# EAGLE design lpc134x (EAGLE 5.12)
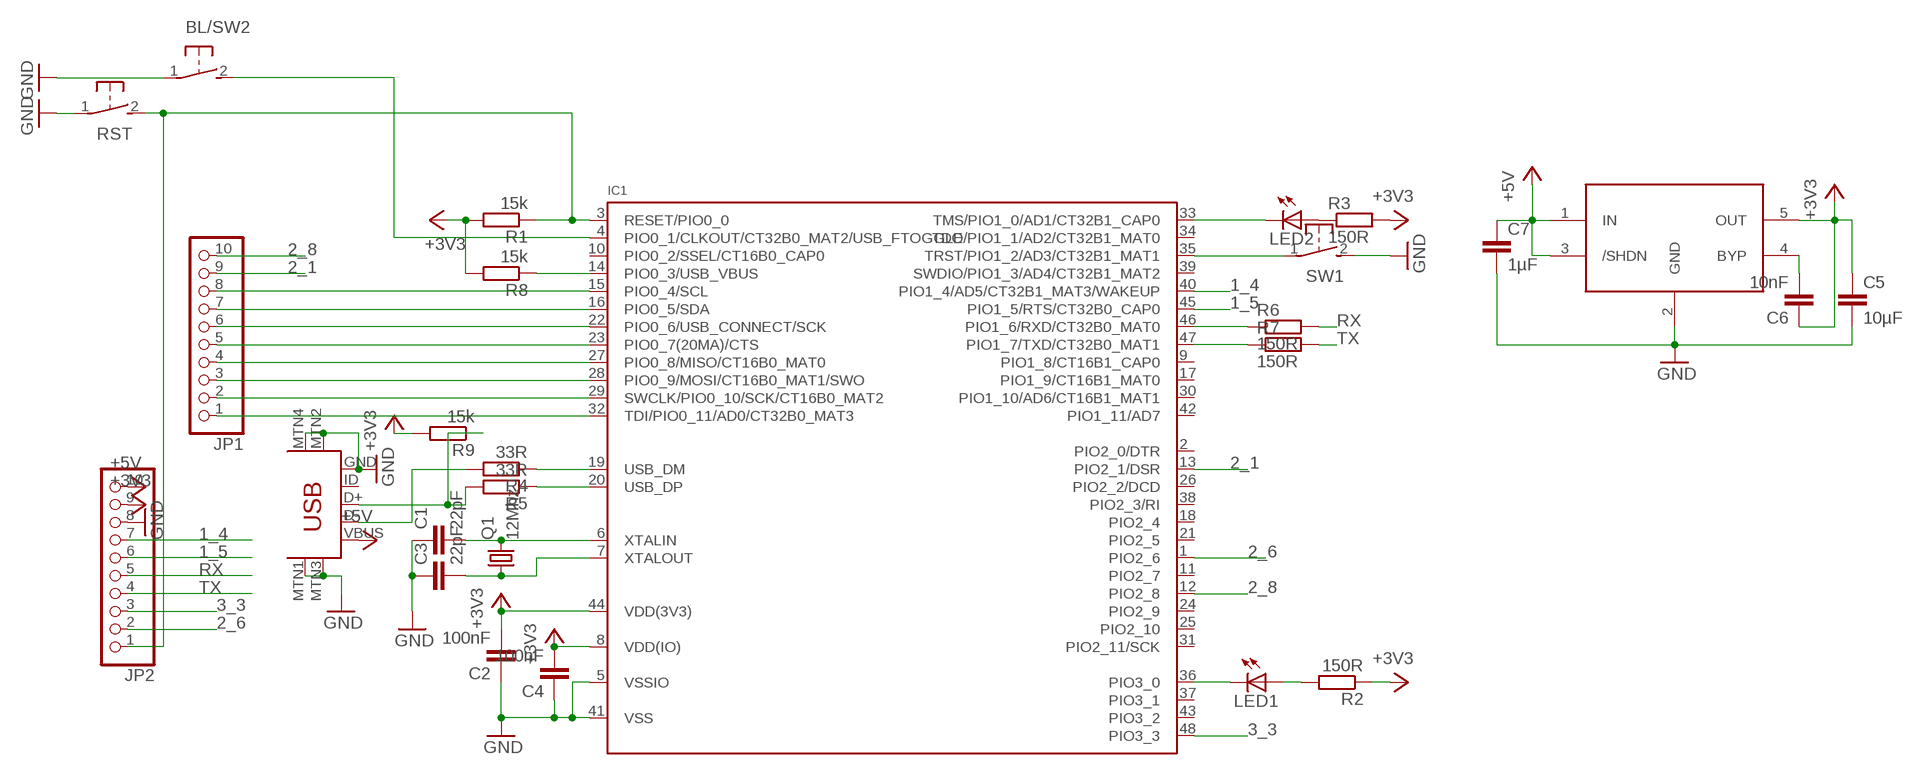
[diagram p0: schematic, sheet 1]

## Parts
BL/SW2  SWITCH_MCTAEF  [SWITCH_MCTAEF]
C1  22pF  C-EUC0402  [C0402]
C2  100nF  C-EUC0402  [C0402]
C3  22pF  C-EUC0402  [C0402]
C4  100nF  C-EUC0402  [C0402]
C5  10µF  CAP0805  [0805]
C6  10nF  C-EUC0402  [C0402]
C7  1µF  CAP0805  [0805]
IC1  LPC1343_QFP  [LQFP48]
IC2  LT1761  [SOT23-5L]
JP1  PINHD-1X10_2.54  [1X10]
JP2  PINHD-1X10_2.54  [1X10]
LED1  LEDCHIPLED_0805  [CHIPLED_0805]
LED2  LEDCHIPLED_0805  [CHIPLED_0805]
Q1  12Mhz  MT-OSCILLATOR  [MT]
R1  15k  R-EU_R0402  [R0402]
R2  150R  R-EU_R0402  [R0402]
R3  150R  R-EU_R0402  [R0402]
R4  33R  R-EU_R0402  [R0402]
R5  33R  R-EU_R0402  [R0402]
R6  150R  R-EU_R0402  [R0402]
R7  150R  R-EU_R0402  [R0402]
R8  15k  R-EU_R0402  [R0402]
R9  15k  R-EU_R0402  [R0402]
RST  SWITCH_MCTAEF  [SWITCH_MCTAEF]
SW1  SWITCH_MCTAEF  [SWITCH_MCTAEF]
U$1  USB-MINIB-5PIN  [USB-MINIB]

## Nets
1_4: IC1.40(PIO1_4/AD5/CT32B1_MAT3/WAKEUP) JP2.7
1_5: IC1.45(PIO1_5/RTS/CT32B0_CAP0) JP2.6
2_1: IC1.13(PIO2_1/DSR) JP1.9
2_6: IC1.1(PIO2_6) JP2.2
2_8: IC1.12(PIO2_8) JP1.10
3_3: IC1.48(PIO3_3) JP2.3
+3V3: C2.2 C4.2 C5.1 C6.1 IC1.8(VDD(IO)) IC1.44(VDD(3V3)) IC2.5(OUT) JP2.9 R1.2 R2.1 R3.2 R8.2 R9.2
+5V: C7.1 IC2.1(IN) IC2.3(/SHDN) JP2.10 U$1.VBUS
GND: BL/SW2.1 C1.1 C2.1 C3.1 C4.1 C5.2 C7.2 IC1.5(VSSIO) IC1.41(VSS) IC2.2(GND) JP2.8 RST.1 SW1.2 U$1.GND U$1.MTN1(MTN2) U$1.MTN2(MTN3) U$1.MTN3(MTN1) U$1.MTN4
N$1: IC1.32(TDI/PIO0_11/AD0/CT32B0_MAT3) JP1.1
N$2: IC1.29(SWCLK/PIO0_10/SCK/CT16B0_MAT2) JP1.2
N$3: C3.2 IC1.7(XTALOUT) Q1.1
N$4: C1.2 IC1.6(XTALIN) Q1.3
N$5: IC1.28(PIO0_9/MOSI/CT16B0_MAT1/SWO) JP1.3
N$6: IC1.27(PIO0_8/MISO/CT16B0_MAT0) JP1.4
N$7: IC1.3(RESET/PIO0_0) JP2.1 R1.1 RST.2
N$8: IC1.23(PIO0_7(20MA)/CTS) JP1.5
N$9: IC1.22(PIO0_6/USB_CONNECT/SCK) JP1.6
N$10: R5.2 R9.1 U$1.D+
N$11: R4.2 U$1.D-
N$12: IC1.14(PIO0_3/USB_VBUS) R8.1
N$14: IC1.19(USB_DM) R4.1
N$16: IC1.46(PIO1_6/RXD/CT32B0_MAT0) R6.1
N$17: IC1.47(PIO1_7/TXD/CT32B0_MAT1) R7.1
N$18: LED1.A R2.2
N$19: IC1.36(PIO3_0) LED1.C
N$20: IC1.35(TRST/PIO1_2/AD3/CT32B1_MAT1) SW1.1
N$21: BL/SW2.2 IC1.4(PIO0_1/CLKOUT/CT32B0_MAT2/USB_FTOGGLE)
N$22: LED2.A R3.1
N$23: IC1.33(TMS/PIO1_0/AD1/CT32B1_CAP0) LED2.C
N$24: IC1.20(USB_DP) R5.1
N$43: C6.2 IC2.4(BYP)
RX: JP2.5 R6.2
SCL: IC1.15(PIO0_4/SCL) JP1.8
SDA: IC1.16(PIO0_5/SDA) JP1.7
TX: JP2.4 R7.2
Unconnected: IC1.2(PIO2_0/DTR) IC1.9(PIO1_8/CT16B1_CAP0) IC1.10(PIO0_2/SSEL/CT16B0_CAP0) IC1.11(PIO2_7) IC1.17(PIO1_9/CT16B1_MAT0) IC1.18(PIO2_4) IC1.21(PIO2_5) IC1.24(PIO2_9) IC1.25(PIO2_10) IC1.26(PIO2_2/DCD) IC1.30(PIO1_10/AD6/CT16B1_MAT1) IC1.31(PIO2_11/SCK) IC1.34(TDO/PIO1_1/AD2/CT32B1_MAT0) IC1.37(PIO3_1) IC1.38(PIO2_3/RI) IC1.39(SWDIO/PIO1_3/AD4/CT32B1_MAT2) IC1.42(PIO1_11/AD7) IC1.43(PIO3_2) U$1.ID

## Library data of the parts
BL/SW2 RST SW1 = seb:SWITCH_MCTAEF
C1-C4 C6 = rcl:C-EU: CAPACITOR, European symbol
C5 C7 = SparkFun:CAP: Capacitor
IC1 = microbuilder:LPC1343_QFP: LPC1343 72 MHz 32-bit ARM Cortex-M3 microcontroller. 32 kB Flash, 8 kB SRAM, USB Device Mouser: 771-LPC1343FBD48151 Digikey: 568-4945-ND; DIGIKEY#: 568-4945-ND; MANF: NXP; MANF#: LPC1343FBD48,151
IC2 = seb:LT1761
JP1 JP2 = pinhead-2:PINHD-1X10: PIN HEADER
LED1 LED2 = led:LED: LED
Q1 = seb:MT-OSCILLATOR
R1-R9 = rcl:R-EU_: RESISTOR, European symbol
U$1 = SparkFun:USB-MINIB: Mini-USB "B" connector with 5th pin broken out. Created new symbol breaking out 5th "ID" pin in mini/micro USB connector spec. See: http://en.wikipedia.org/wiki/Mini_usb#Cables. Uses same footprint as 4-pin symbol. Also added pins to connect to mounting / shield pads if required (probably not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

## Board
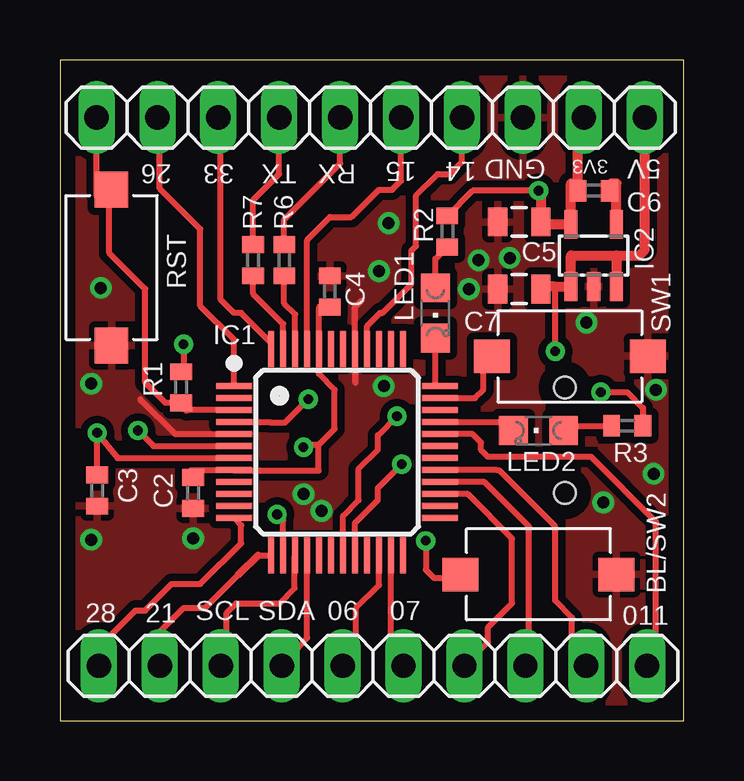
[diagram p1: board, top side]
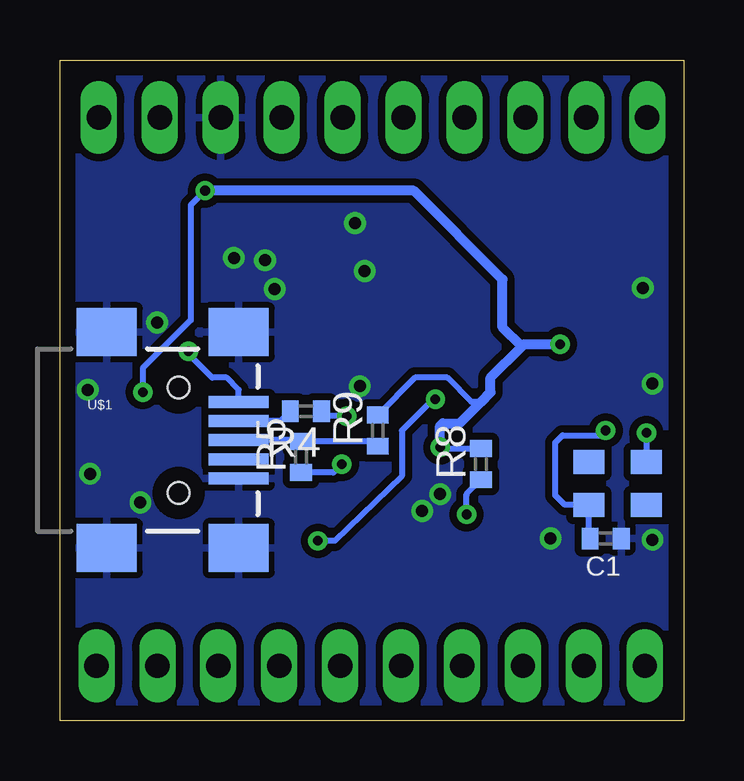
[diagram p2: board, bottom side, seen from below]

Size 26 x 27.55 mm. Coordinates in mm from the lower left corner, seen from the top.
Outline: 0,0 26,0 26,27.55 0,27.55 0,0
Copper layers (1*16): Top 0.035mm / dielectric 1.5mm / Bottom 0.035mm
Design rules "default *": minimum track width 10mil, minimum drill 24mil, track to track 8mil, track to pad 8mil, pad to pad 8mil, via to via 8mil, smd to smd 8mil, copper to edge 25mil, drill to drill 8mil, minimum pad ring 10mil, minimum via ring 8mil, stop-mask expansion 4mil, vias tented up to drill 40mil, thermal gap 10mil

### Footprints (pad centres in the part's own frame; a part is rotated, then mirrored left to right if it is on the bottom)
SWITCH_MCTAEF = smd 1.5 x 1.4: 1 -3.25,0; 2 3.25,0
C0402 = smd 0.7 x 0.9: 1 -0.65,0; 2 0.65,0
0805 = smd 0.8 x 1.2: 1 -0.9,0; 2 0.9,0
LQFP48 = smd 1.5 x 0.25: 1 -4.3,2.75; 2 -4.3,2.25; 3 -4.3,1.75; 4 -4.3,1.25; 5 -4.3,0.75; 6 -4.3,0.25; 7 -4.3,-0.25; 8 -4.3,-0.75; 9 -4.3,-1.25; 10 -4.3,-1.75; 11 -4.3,-2.25; 12 -4.3,-2.75; 25 4.3,-2.75; 26 4.3,-2.25; 27 4.3,-1.75; 28 4.3,-1.25; 29 4.3,-0.75; 30 4.3,-0.25; 31 4.3,0.25; 32 4.3,0.75; 33 4.3,1.25; 34 4.3,1.75; 35 4.3,2.25; 36 4.3,2.75 | smd 0.25 x 1.5: 13 -2.75,-4.3; 14 -2.25,-4.3; 15 -1.75,-4.3; 16 -1.25,-4.3; 17 -0.75,-4.3; 18 -0.25,-4.3; 19 0.25,-4.3; 20 0.75,-4.3; 21 1.25,-4.3; 22 1.75,-4.3; 23 2.25,-4.3; 24 2.75,-4.3; 37 2.75,4.3; 38 2.25,4.3; 39 1.75,4.3; 40 1.25,4.3; 41 0.75,4.3; 42 0.25,4.3; 43 -0.25,4.3; 44 -0.75,4.3; 45 -1.25,4.3; 46 -1.75,4.3; 47 -2.25,4.3; 48 -2.75,4.3
SOT23-5L = smd 0.55 x 1.2: 1 -0.95,-1.3; 2 0,-1.3; 3 0.95,-1.3; 4 0.95,1.3; 5 -0.95,1.3
1X10 = drill 1.016 long: 1 -11.43,0; 2 -8.89,0; 3 -6.35,0; 4 -3.81,0; 5 -1.27,0; 6 1.27,0; 7 3.81,0; 8 6.35,0; 9 8.89,0; 10 11.43,0
CHIPLED_0805 = smd 1.2 x 1.2: A 0,-1.05; C 0,1.05
MT = smd 1.3 x 1: 1 1.2,0.9; 2 -1.2,0.9; 3 -1.2,-0.9; 4 1.2,-0.9
R0402 = smd 0.7 x 0.9: 1 -0.65,0; 2 0.65,0
USB-MINIB = smd 2.5 x 0.5: D+ 2.5,0; D- 2.5,0.8; GND 2.5,-1.6; ID 2.5,-0.8; VBUS 2.5,1.6 | smd 2.5 x 2: MTN1 -3,4.5; MTN2 2.5,4.5; MTN3 -3,-4.5; MTN4 2.5,-4.5 | hole 0.9: 0,2.2; 0,-2.2

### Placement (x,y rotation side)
BL/SW2  19.95,6.1 180 top
C1  3.25,7.6 180 bottom
C2  5.55,9.5 90 top
C3  1.55,9.6 90 top
C4  11.25,17.9 270 top
C5  19.15,20.8 180 top
C6  22.25,22.1 0 top
C7  19.15,18 180 top
IC1  11.55,11.2 0 top
IC2  22.25,19.4 0 top
JP1  13.05,2.29 180 top
JP2  12.95,25.15 0 top
LED1  15.65,17 180 top
LED2  19.95,12.1 90 top
Q1  2.75,9.9 0 bottom
R1  5.05,13.9 90 top
R2  16.15,20.4 270 top
R3  23.65,12.3 0 top
R4  15.75,12.9 180 bottom
R5  15.95,11 90 bottom
R6  9.35,19.2 90 top
R7  8.05,19.2 90 top
R8  8.45,10.7 90 bottom
R9  12.75,12.1 90 bottom
RST  2.15,18.9 90 top
SW1  21.25,15.2 0 top
U$1  21.05,11.7 0 bottom

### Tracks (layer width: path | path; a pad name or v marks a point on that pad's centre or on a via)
1_4
  Top 0.254: JP2.7 16.76,23.31 16.25,22.8 15.75,22.8 14.85,21.9 14.85,19.8 14.65,19.6 14.65,18.2 13.45,17 13.35,17 12.8,16.45 IC1.40
1_5
  Top 0.254: JP2.6 14.22,22.51 13.85,22.14 13.29,22.14 12.15,21 11.25,21 10.3,20.05 10.3,20.01 IC1.45
2_1
  Top 0.254: JP1.9 4.16,3.71 5.15,4.7 6.05,4.7 7.45,6.1 | 8.25,6.9 IC1.13
  Top 0.305: 7.45,6.1 8.25,6.9
2_6
  Top 0.254: JP2.2 4.16,25.05 4.16,22.19 5.85,20.5 5.85,17.3 7.23,15.92 7.25,15.9 IC1.1
2_8
  Top 0.254: JP1.10 1.62,3.07 3.15,4.6 3.55,4.6 4.65,5.7 5.85,5.7 7.55,7.4 7.55,8.15 IC1.12
3_3
  Top 0.254: JP2.3 6.7,25.05 6.7,17.56 7.26,17 7.55,17 8.8,15.75 IC1.48
+3V3  (via drill 0.4)
  Top 0.254: 10.78,11.5 10.78,10.43 7.27,10.43 IC1.8 5.45,10.45 5.45,10.4 5.55,10.4 C2.2 | v10.15,11.4 10.25,11.5 10.78,11.5 | R1.2 5.15,14.55 v5.15,15.7 | R2.1 17.2,22.1 v19.95,22.1 | R3.2 24.3,13.05 23.65,13.7 v22.55,13.7 | 10.78,11.5 11.45,12.17 11.45,13.8 10.78,14.47 10.8,14.49 IC1.44 10.8,17.25 C4.2
  Top 0.406: JP2.9 21.6,24.91 C6.1 21.5,22.4 21.3,22.4 IC2.5 20.15,20.7 C5.1 20.05,22 v19.95,22.1
  Bottom 0.254: v22.55,13.7 22.55,14.7 20.55,16.7 20.55,21.5 v19.95,22.1 | R8.2 10.1,11.35 v10.15,11.4 | R9.2 11.2,14.3 9.85,14.3 8.85,13.3 8.45,13.3
  Bottom 0.406: 6.75,15.6 8.05,14.3 8.05,13.7 8.45,13.3 9.35,12.4 10.05,12.4 10.15,12.3 v10.15,11.4 | 6.75,15.6 6.65,15.7 v5.15,15.7 | v19.95,22.1 11.25,22.1 7.55,18.4 7.55,16.4 6.75,15.6
+5V  (via drill 0.4)
  Top 0.254: v20.65,15.4 20.65,18.1
  Top 0.406: 23.2,19.4 IC2.3 | 23.2,19.4 21.3,19.4 IC2.1 20.65,18.1 20.15,18.1 C7.1 | JP2.10 24.38,19.63 24.15,19.4 23.2,19.4
  Bottom 0.254: v20.65,15.4 20.65,15.3 19.65,14.3 19.05,14.3 18.55,13.8 U$1.VBUS
GND  (via drill 0.5)
  Top 0.254: 12.55,17.5 12.3,17.25 IC1.41 12.3,14.1 | IC1.5 4.8,11.95 3.35,13.4
  other vias: 10.15,9.45 1.3,7.55 5.55,7.6 22.65,9.1 24.75,10.3 21.95,16.6 18.75,19.3 17.45,19.2 17.05,18 1.7,18.05 1.3,14.05 13.3,18.75 13.7,20.75 13.5,13.95 10.9,8.75 24.85,13.8
  pour Top (isolate 0.305): 0,0.4 26,0.4 26,27.15 0,27.15
  pour Bottom (isolate 0.305): 0,0.4 26,0.4 26,27.15 0,27.15
N$1
  Top 0.254: JP1.1 24.85,3.26 24.85,8.3 22.15,11 17.85,11 17.55,11.3 17.55,11.6 17.22,11.93 17.2,11.95 IC1.32
N$2
  Top 0.254: JP1.2 21.35,2.99 21.35,4.3 20.65,5 20.65,8.1 18.32,10.43 18.2,10.45 IC1.29
N$3  (via drill 0.4)
  Top 0.254: IC1.7 2.4,10.95 v1.55,12 C3.2
  Bottom 0.254: v1.55,12 Q1.1
N$4  (via drill 0.4)
  Top 0.254: IC1.6 3.9,11.45 v3.25,12.1
  Bottom 0.254: v3.25,12.1 3.45,11.9 5.05,11.9 5.35,11.6 5.35,9.4 4.95,9 Q1.3 3.95,7.65 C1.2
N$5
  Top 0.254: JP1.3 19.55,2.25 19.55,8.1 17.72,9.93 17.7,9.95 IC1.28
N$6
  Top 0.254: JP1.4 17.85,3.28 17.85,3.9 18.85,4.9 18.85,7.6 17.02,9.43 17,9.45 IC1.27
N$7
  Top 0.254: R1.1 5.27,12.93 | JP2.1 1.52,21.88 2.05,21.95 2.05,19.5 3.55,18 3.55,14.1 4.4,13.25 R1.1 | IC1.3 5.35,12.95 R1.1
  Top 0.406: RST.2 2.05,22.15 2.05,21.95
N$8
  Top 0.254: JP1.5 13.78,2.94 13.8,2.96 IC1.23
N$9
  Top 0.254: JP1.6 12.35,2.97 12.35,4.7 13.28,5.63 13.3,5.65 IC1.22
N$10
  Bottom 0.254: U$1.D+ 16,11.7 R5.2 12.95,11.65 R9.1
N$11
  Bottom 0.254: U$1.D- 16.8,12.5 R4.2
N$12  (via drill 0.4)
  Top 0.254: IC1.14 9.3,8.35 v9.05,8.6
  Bottom 0.254: v9.05,8.6 9.05,9.4 9.05,9.45 R8.1
N$14  (via drill 0.4)
  Top 0.254: IC1.19 11.8,8.55 12.45,9.2 12.45,10.5 13.25,11.3 13.25,11.9 v14.05,12.7
  Bottom 0.254: v14.05,12.7 14.9,12.7 R4.1
N$16
  Top 0.254: IC1.46 9.8,16.95 9.35,17.4 R6.1
N$17
  Top 0.254: IC1.47 9.3,16.55 8.05,17.8 R7.1
N$18
  Top 0.254: R2.2 15.65,19.25 LED1.A
N$19
  Top 0.254: 15.83,15.63 LED1.C 15.65,13.95 IC1.36
N$20
  Top 0.254: 17.9,15.5 17.65,14.85 17.65,13.8 17.3,13.45 IC1.35
  Top 0.406: 17.9,15.5 18,15.5 SW1.1
N$21  (via drill 0.4)
  Top 0.254: v10.35,13.4 9.38,12.43 8.78,12.43 8.76,12.45 IC1.4 | 16.6,5.8 16.45,5.95 15.6,5.95 15.25,6.3 v15.25,7.5
  Top 0.406: BL/SW2.2 16.6,6.1 16.6,5.8
  Bottom 0.254: v10.35,13.4 10.45,13.4 11.75,12.1 11.75,10.2 14.55,7.5 v15.25,7.5
N$22
  Top 0.254: R3.1 21,12.3 LED2.A
N$23
  Top 0.254: 18.67,12.43 LED2.C 18.65,12.45 IC1.33
N$24  (via drill 0.4)
  Top 0.254: v14.25,10.7 13.25,9.7 13.25,9.2 12.45,8.4 12.3,8.25 IC1.20
  Bottom 0.254: R5.1 14.6,10.35 v14.25,10.7
N$43
  Top 0.406: IC2.4 23.2,22.4 23,22.4 C6.2
RX
  Top 0.254: JP2.5 11.68,23.23 9.35,20.9 R6.2
SCL
  Top 0.254: JP1.8 6.95,2.65 6.95,4.5 7.35,4.9 9.15,4.9 9.78,5.53 9.78,6.88 IC1.15
SDA
  Top 0.254: JP1.7 10.28,3.44 10.3,3.46 IC1.16
TX
  Top 0.254: JP2.4 9.14,22.79 8.05,21.7 R7.2

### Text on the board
tNames: 26 | 33 | TX | RX | 15 | 14 | GND | 3V3 | 5V | 28 | 21 | SCL | SDA | 06 | 07 | 011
